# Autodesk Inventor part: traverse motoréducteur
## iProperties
Shininess: 64.0
Length Units: 11269
Angle Units: 11279
Time Units: 11290
Mass Units: 11283
Length Display Precision: 3
Angle Display Precision: 2
Compacted: True
Part Number: traverse motoréducteur
Document SubType Name: Modeling
Created: 2005-02
Material: Par défaut
Designer: LEGERET Philippe
Density: 0.0
Volumn: 0.0
Area: 0.0
PropertySet Name: Model Information
Control State: 0
Master: False
Checked Out: False
Author: LEGERET Philippe
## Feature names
1. Extrusion1
2. Perçage1 [Hole]
3. Perçage2 [Hole]
4. Perçage3 [Hole]
5. Réseau circulaire1 [Circular Pattern]
